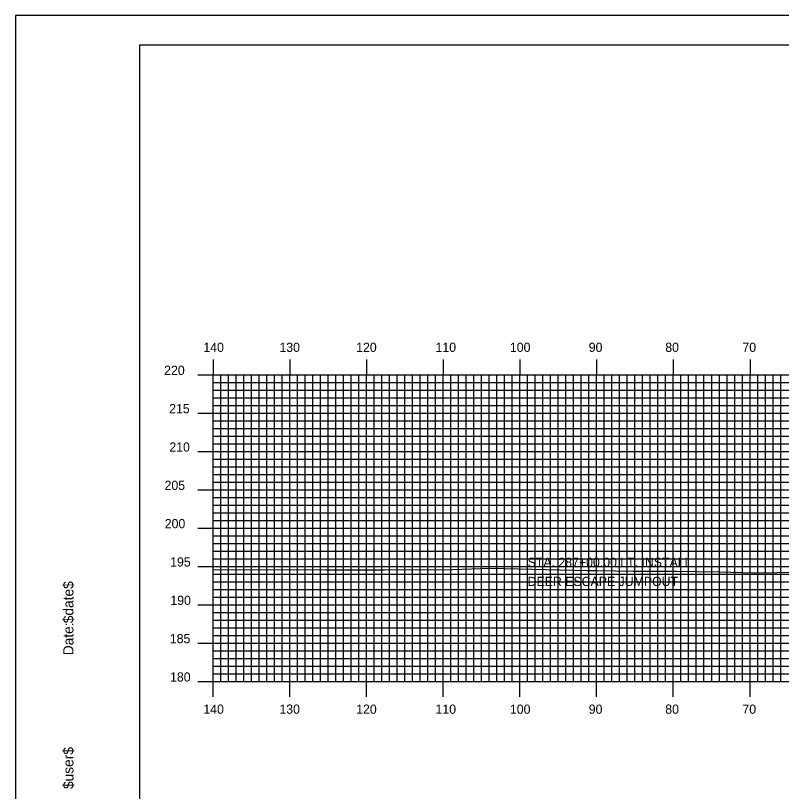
# Model space of a CAD drawing. Extents: x 1812554 to 1812897, y 442591 to 442811.
# Drawn here: x 1812554.2 to 1812654, y 442709.3 to 442810.5 of the extents above; entities that cross this region are included whole.
import ezdxf

# ---------------------------------------------------------------- set-up
doc = ezdxf.new("R2010")
doc.units = 0
for name, color, linetype in [('BORDER', 7, 'Continuous'), ('D_Text_Standard', 7, 'Continuous'), ('H_V ANNOTATION', 7, 'Continuous'), ('MAJOR', 7, 'Continuous'), ('MINOR', 7, 'Continuous'), ('PLOT BOUNDARY', 7, 'Continuous'), ('S_Roadway_Centerline', 7, 'Continuous')]:
    doc.layers.add(name, color=color, linetype=linetype)

msp = doc.modelspace()

# ---------------------------------------------------------------- linework, layer by layer
at = {"layer": 'BORDER'}
msp.add_lwpolyline([(1812570.34, 442596.67), (1812890.34, 442596.67), (1812890.34, 442806.67), (1812570.34, 442806.67)], close=True, dxfattribs=at)
at = {"layer": 'MAJOR'}
for p, q in [((1812579.94, 442765.67), (1812579.94, 442763.67)), ((1812589.94, 442765.67), (1812589.94, 442763.67)), ((1812599.94, 442765.67), (1812599.94, 442763.67)), ((1812609.94, 442765.67), (1812609.94, 442763.67)), ((1812619.94, 442765.67), (1812619.94, 442763.67)), ((1812629.94, 442765.67), (1812629.94, 442763.67)), ((1812639.94, 442765.67), (1812639.94, 442763.67)), ((1812649.94, 442765.67), (1812649.94, 442763.67)), ((1812577.94, 442763.67), (1812579.94, 442763.67)), ((1812579.94, 442763.67), (1812859.94, 442763.67)), ((1812579.94, 442723.67), (1812579.94, 442763.67)), ((1812579.94, 442723.67), (1812579.94, 442763.67)), ((1812579.94, 442763.67), (1812859.94, 442763.67)), ((1812589.94, 442723.67), (1812589.94, 442763.67)), ((1812599.94, 442723.67), (1812599.94, 442763.67)), ((1812609.94, 442723.67), (1812609.94, 442763.67)), ((1812619.94, 442723.67), (1812619.94, 442763.67)), ((1812629.94, 442723.67), (1812629.94, 442763.67)), ((1812639.94, 442723.67), (1812639.94, 442763.67)), ((1812649.94, 442723.67), (1812649.94, 442763.67)), ((1812577.94, 442758.67), (1812579.94, 442758.67)), ((1812579.94, 442758.67), (1812859.94, 442758.67)), ((1812577.94, 442753.67), (1812579.94, 442753.67)), ((1812579.94, 442753.67), (1812859.94, 442753.67)), ((1812577.94, 442748.67), (1812579.94, 442748.67)), ((1812579.94, 442748.67), (1812859.94, 442748.67)), ((1812577.94, 442743.67), (1812579.94, 442743.67)), ((1812579.94, 442743.67), (1812859.94, 442743.67)), ((1812577.94, 442738.67), (1812579.94, 442738.67)), ((1812579.94, 442738.67), (1812859.94, 442738.67)), ((1812577.94, 442733.67), (1812579.94, 442733.67)), ((1812579.94, 442733.67), (1812859.94, 442733.67)), ((1812577.94, 442728.67), (1812579.94, 442728.67)), ((1812579.94, 442728.67), (1812859.94, 442728.67)), ((1812577.94, 442723.67), (1812579.94, 442723.67)), ((1812579.94, 442723.67), (1812859.94, 442723.67)), ((1812579.94, 442723.67), (1812859.94, 442723.67)), ((1812579.94, 442721.66), (1812579.94, 442723.67)), ((1812589.94, 442721.66), (1812589.94, 442723.67)), ((1812599.94, 442721.66), (1812599.94, 442723.67)), ((1812609.94, 442721.66), (1812609.94, 442723.67)), ((1812619.94, 442721.66), (1812619.94, 442723.67)), ((1812629.94, 442721.66), (1812629.94, 442723.67)), ((1812639.94, 442721.66), (1812639.94, 442723.67)), ((1812649.94, 442721.66), (1812649.94, 442723.67))]:
    msp.add_line(p, q, dxfattribs=at)
at = {"layer": 'MINOR'}
for p, q in [((1812580.94, 442723.67), (1812580.94, 442763.67)), ((1812581.94, 442723.67), (1812581.94, 442763.67)), ((1812582.94, 442723.67), (1812582.94, 442763.67)), ((1812583.94, 442723.67), (1812583.94, 442763.67)), ((1812584.94, 442723.67), (1812584.94, 442763.67)), ((1812585.94, 442723.67), (1812585.94, 442763.67)), ((1812586.94, 442723.67), (1812586.94, 442763.67)), ((1812587.94, 442723.67), (1812587.94, 442763.67)), ((1812588.94, 442723.67), (1812588.94, 442763.67)), ((1812590.94, 442723.67), (1812590.94, 442763.67)), ((1812591.94, 442723.67), (1812591.94, 442763.67)), ((1812592.94, 442723.67), (1812592.94, 442763.67)), ((1812593.94, 442723.67), (1812593.94, 442763.67)), ((1812594.94, 442723.67), (1812594.94, 442763.67)), ((1812595.94, 442723.67), (1812595.94, 442763.67)), ((1812596.94, 442723.67), (1812596.94, 442763.67)), ((1812597.94, 442723.67), (1812597.94, 442763.67)), ((1812598.94, 442723.67), (1812598.94, 442763.67)), ((1812600.94, 442723.67), (1812600.94, 442763.67)), ((1812601.94, 442723.67), (1812601.94, 442763.67)), ((1812602.94, 442723.67), (1812602.94, 442763.67)), ((1812603.94, 442723.67), (1812603.94, 442763.67)), ((1812604.94, 442723.67), (1812604.94, 442763.67)), ((1812605.94, 442723.67), (1812605.94, 442763.67)), ((1812606.94, 442723.67), (1812606.94, 442763.67)), ((1812607.94, 442723.67), (1812607.94, 442763.67)), ((1812608.94, 442723.67), (1812608.94, 442763.67)), ((1812610.94, 442723.67), (1812610.94, 442763.67)), ((1812611.94, 442723.67), (1812611.94, 442763.67)), ((1812612.94, 442723.67), (1812612.94, 442763.67)), ((1812613.94, 442723.67), (1812613.94, 442763.67)), ((1812614.94, 442723.67), (1812614.94, 442763.67)), ((1812615.94, 442723.67), (1812615.94, 442763.67)), ((1812616.94, 442723.67), (1812616.94, 442763.67)), ((1812617.94, 442723.67), (1812617.94, 442763.67)), ((1812618.94, 442723.67), (1812618.94, 442763.67)), ((1812620.94, 442723.67), (1812620.94, 442763.67)), ((1812621.94, 442723.67), (1812621.94, 442763.67)), ((1812622.94, 442723.67), (1812622.94, 442763.67)), ((1812623.94, 442723.67), (1812623.94, 442763.67)), ((1812624.94, 442723.67), (1812624.94, 442763.67)), ((1812625.94, 442723.67), (1812625.94, 442763.67)), ((1812626.94, 442723.67), (1812626.94, 442763.67)), ((1812627.94, 442723.67), (1812627.94, 442763.67)), ((1812628.94, 442723.67), (1812628.94, 442763.67)), ((1812630.94, 442723.67), (1812630.94, 442763.67)), ((1812631.94, 442723.67), (1812631.94, 442763.67)), ((1812632.94, 442723.67), (1812632.94, 442763.67)), ((1812633.94, 442723.67), (1812633.94, 442763.67)), ((1812634.94, 442723.67), (1812634.94, 442763.67)), ((1812635.94, 442723.67), (1812635.94, 442763.67)), ((1812636.94, 442723.67), (1812636.94, 442763.67)), ((1812637.94, 442723.67), (1812637.94, 442763.67)), ((1812638.94, 442723.67), (1812638.94, 442763.67)), ((1812640.94, 442723.67), (1812640.94, 442763.67)), ((1812641.94, 442723.67), (1812641.94, 442763.67)), ((1812642.94, 442723.67), (1812642.94, 442763.67)), ((1812643.94, 442723.67), (1812643.94, 442763.67)), ((1812644.94, 442723.67), (1812644.94, 442763.67)), ((1812645.94, 442723.67), (1812645.94, 442763.67)), ((1812646.94, 442723.67), (1812646.94, 442763.67)), ((1812647.94, 442723.67), (1812647.94, 442763.67)), ((1812648.94, 442723.67), (1812648.94, 442763.67)), ((1812650.94, 442723.67), (1812650.94, 442763.67)), ((1812651.94, 442723.67), (1812651.94, 442763.67)), ((1812652.94, 442723.67), (1812652.94, 442763.67)), ((1812653.94, 442723.67), (1812653.94, 442763.67)), ((1812579.94, 442762.67), (1812859.94, 442762.67)), ((1812579.94, 442762.67), (1812581.95, 442762.67)), ((1812579.94, 442761.67), (1812859.94, 442761.67)), ((1812579.94, 442761.67), (1812581.95, 442761.67)), ((1812579.94, 442760.67), (1812859.94, 442760.67)), ((1812579.94, 442760.67), (1812581.95, 442760.67)), ((1812579.94, 442759.67), (1812859.94, 442759.67)), ((1812579.94, 442759.67), (1812581.95, 442759.67)), ((1812579.94, 442757.67), (1812859.94, 442757.67)), ((1812579.94, 442757.67), (1812581.95, 442757.67)), ((1812579.94, 442756.67), (1812859.94, 442756.67)), ((1812579.94, 442756.67), (1812581.95, 442756.67)), ((1812579.94, 442755.67), (1812859.94, 442755.67)), ((1812579.94, 442755.67), (1812581.95, 442755.67)), ((1812579.94, 442754.67), (1812859.94, 442754.67)), ((1812579.94, 442754.67), (1812581.95, 442754.67)), ((1812579.94, 442752.67), (1812859.94, 442752.67)), ((1812579.94, 442752.67), (1812581.95, 442752.67)), ((1812579.94, 442751.67), (1812859.94, 442751.67)), ((1812579.94, 442751.67), (1812581.95, 442751.67)), ((1812579.94, 442750.67), (1812859.94, 442750.67)), ((1812579.94, 442750.67), (1812581.95, 442750.67)), ((1812579.94, 442749.67), (1812859.94, 442749.67)), ((1812579.94, 442749.67), (1812581.95, 442749.67)), ((1812579.94, 442747.67), (1812859.94, 442747.67)), ((1812579.94, 442747.67), (1812581.95, 442747.67)), ((1812579.94, 442746.67), (1812859.94, 442746.67)), ((1812579.94, 442746.67), (1812581.95, 442746.67)), ((1812579.94, 442745.67), (1812859.94, 442745.67)), ((1812579.94, 442745.67), (1812581.95, 442745.67)), ((1812579.94, 442744.67), (1812859.94, 442744.67)), ((1812579.94, 442744.67), (1812581.95, 442744.67)), ((1812579.94, 442742.67), (1812859.94, 442742.67)), ((1812579.94, 442742.67), (1812581.95, 442742.67)), ((1812579.94, 442741.67), (1812859.94, 442741.67)), ((1812579.94, 442741.67), (1812581.95, 442741.67)), ((1812579.94, 442740.67), (1812859.94, 442740.67)), ((1812579.94, 442740.67), (1812581.95, 442740.67)), ((1812579.94, 442739.67), (1812859.94, 442739.67)), ((1812579.94, 442739.67), (1812581.95, 442739.67)), ((1812579.94, 442737.67), (1812859.94, 442737.67)), ((1812579.94, 442737.67), (1812581.95, 442737.67)), ((1812579.94, 442736.67), (1812859.94, 442736.67)), ((1812579.94, 442736.67), (1812581.95, 442736.67)), ((1812579.94, 442735.67), (1812859.94, 442735.67)), ((1812579.94, 442735.67), (1812581.95, 442735.67)), ((1812579.94, 442734.67), (1812859.94, 442734.67)), ((1812579.94, 442734.67), (1812581.95, 442734.67)), ((1812579.94, 442732.67), (1812859.94, 442732.67)), ((1812579.94, 442732.67), (1812581.95, 442732.67)), ((1812579.94, 442731.67), (1812859.94, 442731.67)), ((1812579.94, 442731.67), (1812581.95, 442731.67)), ((1812579.94, 442730.67), (1812859.94, 442730.67)), ((1812579.94, 442730.67), (1812581.95, 442730.67)), ((1812579.94, 442729.67), (1812859.94, 442729.67)), ((1812579.94, 442729.67), (1812581.95, 442729.67)), ((1812579.94, 442727.67), (1812859.94, 442727.67)), ((1812579.94, 442727.67), (1812581.95, 442727.67)), ((1812579.94, 442726.67), (1812859.94, 442726.67)), ((1812579.94, 442726.67), (1812581.95, 442726.67)), ((1812579.94, 442725.67), (1812859.94, 442725.67)), ((1812579.94, 442725.67), (1812581.95, 442725.67)), ((1812579.94, 442724.67), (1812859.94, 442724.67)), ((1812579.94, 442724.67), (1812581.95, 442724.67))]:
    msp.add_line(p, q, dxfattribs=at)
at = {"layer": 'PLOT BOUNDARY'}
msp.add_lwpolyline([(1812554.16, 442590.55), (1812894.16, 442590.55), (1812894.16, 442810.55), (1812554.16, 442810.55)], close=True, dxfattribs=at)
at = {"layer": 'S_Roadway_Centerline'}
msp.add_lwpolyline([(1812579.94, 442738.3), (1812594.62, 442738.25), (1812602.26, 442738.24), (1812611.15, 442738.27), (1812616.05, 442738.47), (1812628.73, 442738.14), (1812630, 442738.16), (1812634.69, 442738.06), (1812640.31, 442738.08), (1812645.87, 442737.99), (1812650.51, 442737.86), (1812662.27, 442738.01)], dxfattribs=at)

# ---------------------------------------------------------------- texts
at = {"layer": 'BORDER'}
for s, p in [('$date$', (1812561.71, 442731.28)), ('Date:', (1812561.71, 442727.1)), ('$user$', (1812561.71, 442709.65))]:
    msp.add_text(s, height=1.339, rotation=90, dxfattribs=at).set_placement(p)
at = {"layer": 'D_Text_Standard'}
for s, p in [('STA. 287+00.00 LT. INSTALL ', (1812620.94, 442738.63)), ('DEER ESCAPE JUMPOUT', (1812620.94, 442736.13))]:
    msp.add_text(s, height=1.2, dxfattribs=at).set_placement(p)
at = {"layer": 'H_V ANNOTATION'}
for s, p in [('140', (1812578.65, 442766.67)), ('130', (1812588.57, 442766.67)), ('120', (1812598.58, 442766.67)), ('110', (1812608.93, 442766.67)), ('100', (1812618.63, 442766.67)), ('90', (1812628.91, 442766.67)), ('80', (1812638.89, 442766.67)), ('70', (1812648.95, 442766.67)), ('220', (1812573.54, 442763.67)), ('215', (1812574.19, 442758.67)), ('210', (1812574.22, 442753.67)), ('205', (1812573.59, 442748.67)), ('200', (1812573.62, 442743.67)), ('195', (1812574.32, 442738.67)), ('190', (1812574.35, 442733.67)), ('185', (1812574.28, 442728.67)), ('180', (1812574.31, 442723.67)), ('140', (1812578.65, 442719.47)), ('130', (1812588.57, 442719.47)), ('120', (1812598.58, 442719.47)), ('110', (1812608.93, 442719.47)), ('100', (1812618.63, 442719.47)), ('90', (1812628.91, 442719.47)), ('80', (1812638.89, 442719.47)), ('70', (1812648.95, 442719.47))]:
    msp.add_text(s, height=1.2, dxfattribs=at).set_placement(p)
at = {"layer": 'MAJOR'}
msp.add_text('-', height=0.012, dxfattribs=at).set_placement((1812579.93, 442723.67))

doc.saveas('drawing.dxf')
